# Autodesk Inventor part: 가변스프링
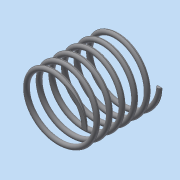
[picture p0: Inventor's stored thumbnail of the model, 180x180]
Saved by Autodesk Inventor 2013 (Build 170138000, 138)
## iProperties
Created: 2018-02
Part Number: 가변스프링
Material: 일반
Document SubType Name: Modeling
Designer: dgall
Density: 1 g/cm^3
Author: dgall
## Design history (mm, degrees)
sketch "스케치1"
  geometry: L1 (0, 0)-(20, 0); L2 (0, 0)-(0, 47.25); L3 (0, 47.25)-(20, 47.25); C1 r 1.5 at (20, 0)
  constraints: 6 end point, 2 perpendicular, 1 centre point, 1 coincident, 1 horizontal, 1 vertical alignment
  dimensions: "d0" = 47.25 distance of L1.start L2.end (derived); "d1" = 40 diameter of L1.end L2; "d2" = 3 diameter of C1
feature "코일1" sketch "스케치1" pitch "d3" = 10; turns "d5" = 6; dims "d4" = 47.25 (= d0), "d6" = 0, angle "d7" = 90 deg, angle "d8" = 90 deg, "d9" = 0, "d10" = 0
node "작업 평면1"
feature "분할1"
feature "분할3"
node "솔리드1"
